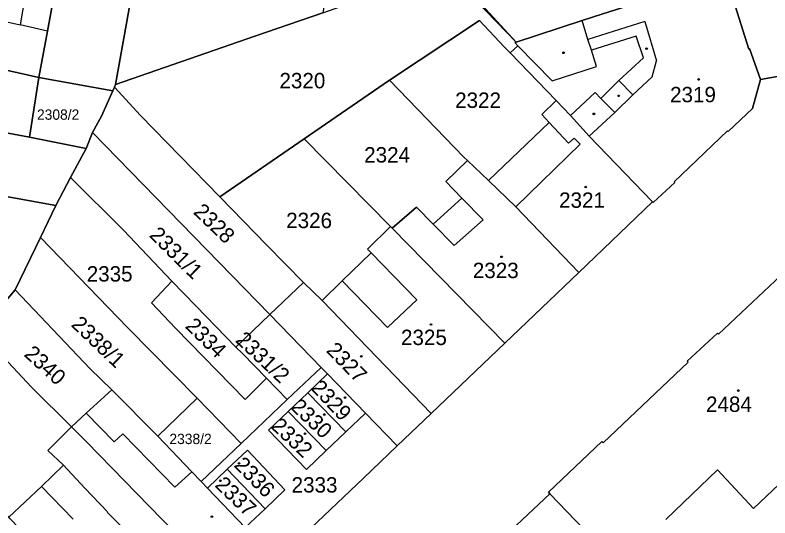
# Model space of a CAD drawing. Extents: x -596233 to -595156, y -1161235 to -1159375.
# Drawn here: x -595870.4 to -595787.2, y -1160442.5 to -1160387 of the extents above; entities that cross this region are included whole.
import ezdxf

# ---------------------------------------------------------------- set-up
doc = ezdxf.new("R2010")
doc.units = 0
for name, color, linetype in [('KN_CAR_KR', 7, 'Continuous'), ('KN_KULTURY', 7, 'Continuous'), ('KN_PARC_CIS_POZ', 7, 'Continuous'), ('KN_PARC_CIS_STAV', 7, 'Continuous'), ('KN_PARC_PLOCHA', 7, 'Continuous'), ('parcely_l', 7, 'Continuous')]:
    doc.layers.add(name, color=color, linetype=linetype)

msp = doc.modelspace()

# ---------------------------------------------------------------- linework, layer by layer
at = {"layer": 'KN_CAR_KR'}
for points in [[(-595865.68, -1160363.58), (-595869.81, -1160388.06)], [(-595873.45, -1160387.23), (-595869.81, -1160388.06)], [(-595807.22, -1160389.66), (-595807.86, -1160387.59)], [(-595800.95, -1160387.7), (-595807.22, -1160389.66)], [(-595800.95, -1160387.7), (-595799.67, -1160392.04)], [(-595866.8, -1160388.74), (-595869.81, -1160388.06)], [(-595801.9, -1160389.3), (-595806.81, -1160390.84)], [(-595801.08, -1160391.71), (-595801.9, -1160389.3)], [(-595814.95, -1160390.36), (-595811.17, -1160394.23)], [(-595806.81, -1160390.84), (-595807.22, -1160389.66)], [(-595806.26, -1160392.65), (-595806.81, -1160390.84)], [(-595803.8, -1160394.21), (-595801.08, -1160391.71)], [(-595811.17, -1160394.23), (-595806.26, -1160392.65)], [(-595800.14, -1160393.78), (-595799.67, -1160392.04)], [(-595805.79, -1160396.2), (-595803.8, -1160394.21)], [(-595803.8, -1160394.21), (-595802.25, -1160395.77)], [(-595802.25, -1160395.77), (-595800.14, -1160393.78)], [(-595809.12, -1160398.06), (-595806.43, -1160395.53)], [(-595806.43, -1160395.53), (-595805.79, -1160396.2)], [(-595804.25, -1160397.73), (-595802.25, -1160395.77)], [(-595805.79, -1160396.2), (-595804.25, -1160397.73)], [(-595807.09, -1160400.34), (-595804.25, -1160397.73)], [(-595811.49, -1160398.84), (-595809.36, -1160401.13)], [(-595809.36, -1160401.13), (-595808.75, -1160400.55)], [(-595808.75, -1160400.55), (-595808.07, -1160401.23)], [(-595808.07, -1160401.23), (-595815.17, -1160408.13)], [(-595818.77, -1160409.59), (-595821.1, -1160407.2)], [(-595824.27, -1160410.07), (-595821.95, -1160412.42)], [(-595821.95, -1160412.42), (-595818.77, -1160409.59)], [(-595831.12, -1160413.22), (-595826.09, -1160418.39)], [(-595829.31, -1160421.46), (-595834.31, -1160416.31)], [(-595826.09, -1160418.39), (-595829.31, -1160421.46)], [(-595859.44, -1160434.09), (-595862.55, -1160430.93)], [(-595779.11, -1160432.11), (-595788.96, -1160441.45)], [(-595858.51, -1160433.19), (-595859.44, -1160434.09)], [(-595852.75, -1160439.09), (-595858.51, -1160433.19)], [(-595865.02, -1160436.67), (-595862.67, -1160439.2)], [(-595850.9, -1160437.38), (-595852.75, -1160439.09)], [(-595792.92, -1160437.19), (-595798.64, -1160442.64)], [(-595788.96, -1160441.45), (-595792.92, -1160437.19)], [(-595867.48, -1160439), (-595863.97, -1160442.6)], [(-595862.67, -1160439.2), (-595860.17, -1160441.8)], [(-595860.17, -1160441.8), (-595860.23, -1160441.86)], [(-595860.23, -1160441.86), (-595856.25, -1160445.86)]]:
    msp.add_lwpolyline(points, dxfattribs=at)
at = {"layer": 'KN_KULTURY'}
for centre, radius in [((-595809.9, -1160391.14), 0.09), ((-595809.9, -1160391.14), 0.0398), ((-595800.75, -1160390.68), 0.09), ((-595800.75, -1160390.68), 0.0398), ((-595795.01, -1160394.08), 0.09), ((-595795.01, -1160394.08), 0.0398), ((-595803.83, -1160395.89), 0.09), ((-595803.83, -1160395.89), 0.0398), ((-595806.56, -1160397.88), 0.09), ((-595806.56, -1160397.88), 0.0398), ((-595807.46, -1160405.96), 0.09), ((-595807.46, -1160405.96), 0.0398), ((-595816.74, -1160413.66), 0.09), ((-595816.74, -1160413.66), 0.0398), ((-595824.52, -1160421.13), 0.09), ((-595824.52, -1160421.13), 0.0398), ((-595832.2, -1160424.65), 0.09), ((-595832.2, -1160424.65), 0.0398), ((-595790.64, -1160428.42), 0.09), ((-595790.64, -1160428.42), 0.0398), ((-595834, -1160429.19), 0.09), ((-595834, -1160429.19), 0.0398), ((-595836.28, -1160431.07), 0.09), ((-595836.28, -1160431.07), 0.0398), ((-595838.41, -1160433.18), 0.09), ((-595838.41, -1160433.18), 0.0398), ((-595845.69, -1160436.46), 0.09), ((-595845.69, -1160436.46), 0.0398), ((-595847.75, -1160438.38), 0.09), ((-595847.75, -1160438.38), 0.0398), ((-595848.68, -1160442.34), 0.09), ((-595848.68, -1160442.34), 0.0398)]:
    msp.add_circle(centre, radius, dxfattribs=at)
at = {"layer": 'KN_PARC_PLOCHA'}
for points in [[(-595858.59, -1160340.56), (-595860.41, -1160351.1), (-595860.54, -1160351.8), (-595861.06, -1160355.69), (-595862.48, -1160364.12), (-595863.62, -1160370.91), (-595863.68, -1160371.29), (-595864.11, -1160374.06), (-595866.8, -1160388.74), (-595867.74, -1160393.87), (-595881.13, -1160390.85), (-595878.76, -1160378.19), (-595876.93, -1160368.38), (-595875.78, -1160362.24), (-595875.17, -1160358.96), (-595873.01, -1160347.61), (-595871.3, -1160338.04), (-595863.4, -1160339.61), (-595863.37, -1160339.46), (-595858.55, -1160340.36)], [(-595792.06, -1160382.52), (-595805.56, -1160386.84), (-595807.86, -1160387.59), (-595815.14, -1160389.97), (-595820.61, -1160383.98), (-595815.78, -1160382.47), (-595815.35, -1160383.84), (-595805.04, -1160380.63), (-595806.23, -1160376.85), (-595804.59, -1160376.28), (-595794.98, -1160373.26)], [(-595855.78, -1160374.96), (-595859.29, -1160394.64), (-595859.43, -1160394.95), (-595859.6, -1160395.34), (-595867.74, -1160393.87), (-595866.8, -1160388.74), (-595864.11, -1160374.06), (-595858.75, -1160375)], [(-595844.98, -1160375.17), (-595839.04, -1160375.28), (-595834.51, -1160375.37), (-595836.46, -1160386.72), (-595843.93, -1160389.3), (-595859.29, -1160394.64), (-595855.78, -1160374.96)], [(-595815.14, -1160389.97), (-595822.83, -1160381.93), (-595815.83, -1160379.67), (-595810.75, -1160378.3), (-595806.23, -1160376.85), (-595805.04, -1160380.63), (-595815.35, -1160383.84), (-595815.78, -1160382.47), (-595820.61, -1160383.98)], [(-595815.14, -1160389.97), (-595815.27, -1160390.02), (-595814.95, -1160390.36), (-595815.8, -1160391.15), (-595816.45, -1160390.48), (-595819.17, -1160387.56), (-595829.08, -1160394.15), (-595838.49, -1160400.65), (-595847.79, -1160407.03), (-595856.56, -1160398.05), (-595859.43, -1160394.95), (-595859.29, -1160394.64), (-595843.93, -1160389.3), (-595836.46, -1160386.72), (-595832.57, -1160385.37), (-595822.83, -1160381.93)], [(-595788.2, -1160394.1), (-595789.07, -1160397.3), (-595791.75, -1160399.82), (-595791.82, -1160399.75), (-595797.7, -1160405.38), (-595797.63, -1160405.45), (-595800.01, -1160407.66), (-595800.08, -1160407.59), (-595807.09, -1160400.34), (-595809.12, -1160398.06), (-595810.73, -1160396.39), (-595815.8, -1160391.15), (-595814.95, -1160390.36), (-595815.27, -1160390.02), (-595815.14, -1160389.97), (-595807.86, -1160387.59), (-595805.56, -1160386.84), (-595792.06, -1160382.52), (-595789.47, -1160390.73), (-595789.39, -1160390.68)], [(-595815.8, -1160391.15), (-595810.73, -1160396.39), (-595812.31, -1160397.96), (-595811.49, -1160398.84), (-595818.18, -1160405.24), (-595820.51, -1160403.01), (-595820.88, -1160402.65), (-595829.08, -1160394.15), (-595819.17, -1160387.56), (-595816.45, -1160390.48)], [(-595900.72, -1160394.38), (-595892.74, -1160395.91), (-595883.15, -1160397.75), (-595882.92, -1160397.8), (-595868.8, -1160400.45), (-595862.55, -1160401.69), (-595864.25, -1160404.89), (-595865.9, -1160408.01), (-595873.02, -1160406.69), (-595875.63, -1160406.2), (-595878.11, -1160405.74), (-595890.43, -1160403.4), (-595907.71, -1160400.15), (-595906.63, -1160394.38), (-595912.54, -1160393.29), (-595913.62, -1160399.04), (-595919.92, -1160397.86), (-595918.74, -1160390.93), (-595904.64, -1160393.63)], [(-595881.13, -1160390.85), (-595867.74, -1160393.87), (-595868.8, -1160400.45), (-595882.92, -1160397.8), (-595883.15, -1160397.75), (-595881.8, -1160390.72)], [(-595859.6, -1160395.34), (-595860.85, -1160398.14), (-595861.84, -1160399.93), (-595862.55, -1160401.69), (-595868.8, -1160400.45), (-595867.74, -1160393.87)], [(-595820.51, -1160403.01), (-595822.9, -1160405.35), (-595821.1, -1160407.2), (-595824.27, -1160410.07), (-595826.13, -1160408.18), (-595828.79, -1160410.51), (-595828.97, -1160410.32), (-595838.49, -1160400.65), (-595829.08, -1160394.15), (-595820.88, -1160402.65)], [(-595847.79, -1160407.03), (-595842.63, -1160412.37), (-595838.56, -1160416.51), (-595842.3, -1160420.04), (-595861.84, -1160399.93), (-595860.85, -1160398.14), (-595859.6, -1160395.34), (-595859.43, -1160394.95), (-595856.56, -1160398.05)], [(-595800.08, -1160407.59), (-595808.22, -1160415.38), (-595815.17, -1160408.13), (-595818.18, -1160405.24), (-595811.49, -1160398.84), (-595812.31, -1160397.96), (-595810.73, -1160396.39), (-595809.12, -1160398.06), (-595807.09, -1160400.34)], [(-595913.62, -1160399.04), (-595907.71, -1160400.15), (-595890.43, -1160403.4), (-595878.11, -1160405.74), (-595875.63, -1160406.2), (-595873.02, -1160406.69), (-595865.9, -1160408.01), (-595867.58, -1160411.51), (-595870.37, -1160417.31), (-595874.3, -1160421.94), (-595874.98, -1160422.78), (-595882, -1160431.18), (-595885.83, -1160435.77), (-595894.39, -1160426.85), (-595893.37, -1160420.66), (-595892.78, -1160417.12), (-595891.8, -1160411.16), (-595903.68, -1160408.85), (-595904.75, -1160408.62), (-595910.92, -1160407.3), (-595912.15, -1160407.04), (-595921.23, -1160405.32), (-595919.92, -1160397.86)], [(-595842.3, -1160420.04), (-595846.03, -1160423.62), (-595850.45, -1160419.06), (-595853.09, -1160416.36), (-595858.43, -1160410.73), (-595864.25, -1160404.89), (-595862.55, -1160401.69), (-595861.84, -1160399.93)], [(-595828.97, -1160410.32), (-595831.53, -1160412.8), (-595831.12, -1160413.22), (-595834.31, -1160416.31), (-595836.51, -1160418.49), (-595838.56, -1160416.51), (-595842.63, -1160412.37), (-595847.79, -1160407.03), (-595838.49, -1160400.65)], [(-595818.18, -1160405.24), (-595815.17, -1160408.13), (-595808.22, -1160415.38), (-595816.38, -1160423.2), (-595828.79, -1160410.51), (-595826.13, -1160408.18), (-595824.27, -1160410.07), (-595821.1, -1160407.2), (-595822.9, -1160405.35), (-595820.51, -1160403.01)], [(-595853.09, -1160416.36), (-595855.35, -1160418.75), (-595852.68, -1160421.52), (-595845, -1160429.4), (-595842.66, -1160427.06), (-595840.36, -1160429.42), (-595845.45, -1160434.27), (-595850.3, -1160429.25), (-595857.94, -1160421.49), (-595867.58, -1160411.51), (-595865.9, -1160408.01), (-595864.25, -1160404.89), (-595858.43, -1160410.73)], [(-595828.79, -1160410.51), (-595816.38, -1160423.2), (-595824.49, -1160430.95), (-595836.51, -1160418.49), (-595834.31, -1160416.31), (-595831.12, -1160413.22), (-595831.53, -1160412.8), (-595828.97, -1160410.32)], [(-595850.3, -1160429.25), (-595854.63, -1160433.44), (-595859.72, -1160428.34), (-595862.11, -1160426.01), (-595870.37, -1160417.31), (-595867.58, -1160411.51), (-595857.94, -1160421.49)], [(-595846.03, -1160423.62), (-595845.31, -1160424.34), (-595842.66, -1160427.06), (-595845, -1160429.4), (-595852.68, -1160421.52), (-595855.35, -1160418.75), (-595853.09, -1160416.36), (-595850.45, -1160419.06)], [(-595836.51, -1160418.49), (-595824.49, -1160430.95), (-595828.23, -1160434.52), (-595831.73, -1160430.92), (-595835.93, -1160426.59), (-595836.63, -1160425.87), (-595842.3, -1160420.04), (-595838.56, -1160416.51)], [(-595859.72, -1160428.34), (-595862.55, -1160430.93), (-595864.16, -1160432.41), (-595868.55, -1160428.03), (-595874.3, -1160421.94), (-595870.37, -1160417.31), (-595862.11, -1160426.01)], [(-595836.63, -1160425.87), (-595840.36, -1160429.42), (-595842.66, -1160427.06), (-595845.31, -1160424.34), (-595846.03, -1160423.62), (-595842.3, -1160420.04)], [(-595864.16, -1160432.41), (-595866.76, -1160435.02), (-595865.02, -1160436.67), (-595867.48, -1160439), (-595871.07, -1160442.41), (-595876.59, -1160436.68), (-595882, -1160431.18), (-595874.98, -1160422.78), (-595874.3, -1160421.94), (-595868.55, -1160428.03)], [(-595835.93, -1160426.59), (-595838.1, -1160428.66), (-595840.28, -1160430.73), (-595842.45, -1160432.8), (-595838.25, -1160437.12), (-595836.08, -1160435.05), (-595833.9, -1160432.99), (-595831.73, -1160430.92), (-595828.23, -1160434.52), (-595831.96, -1160438.08), (-595837.06, -1160442.96), (-595841.55, -1160447.17), (-595845.01, -1160443.54), (-595842.82, -1160441.46), (-595840.63, -1160439.38), (-595844.76, -1160435), (-595846.98, -1160437.11), (-595849.16, -1160439.18), (-595849.85, -1160438.45), (-595845.45, -1160434.27), (-595840.36, -1160429.42), (-595836.63, -1160425.87)], [(-595831.73, -1160430.92), (-595833.9, -1160432.99), (-595838.1, -1160428.66), (-595835.93, -1160426.59)], [(-595854.63, -1160433.44), (-595850.9, -1160437.38), (-595849.85, -1160438.45), (-595849.16, -1160439.18), (-595845.01, -1160443.54), (-595841.55, -1160447.17), (-595845.8, -1160451.23), (-595862.49, -1160434.07), (-595864.16, -1160432.41), (-595862.55, -1160430.93), (-595859.72, -1160428.34)], [(-595845.45, -1160434.27), (-595849.85, -1160438.45), (-595850.9, -1160437.38), (-595854.63, -1160433.44), (-595850.3, -1160429.25)], [(-595833.9, -1160432.99), (-595836.08, -1160435.05), (-595840.28, -1160430.73), (-595838.1, -1160428.66)], [(-595836.08, -1160435.05), (-595838.25, -1160437.12), (-595842.45, -1160432.8), (-595840.28, -1160430.73)], [(-595845.8, -1160451.23), (-595854.57, -1160459.53), (-595870.96, -1160442.53), (-595871.07, -1160442.41), (-595867.48, -1160439), (-595865.02, -1160436.67), (-595866.76, -1160435.02), (-595864.16, -1160432.41), (-595862.49, -1160434.07)], [(-595842.82, -1160441.46), (-595846.98, -1160437.11), (-595844.76, -1160435), (-595840.63, -1160439.38)], [(-595842.82, -1160441.46), (-595845.01, -1160443.54), (-595849.16, -1160439.18), (-595846.98, -1160437.11)], [(-595793.83, -1160470.75), (-595796.23, -1160471.82), (-595798.63, -1160472.88), (-595801.78, -1160474.29), (-595803.29, -1160474.96), (-595803.52, -1160474.43), (-595807.17, -1160476.08), (-595811.47, -1160478.36), (-595817.12, -1160465.97), (-595819.11, -1160461.5), (-595821.3, -1160456.69), (-595819.9, -1160455.4), (-595823.66, -1160451.32), (-595811.43, -1160439.81), (-595803.85, -1160447.7), (-595803.68, -1160447.88), (-595802.69, -1160450.29), (-595799.86, -1160456.8), (-595798.35, -1160460.26), (-595796.73, -1160464.19), (-595795.91, -1160466.03), (-595794.67, -1160468.86)]]:
    msp.add_lwpolyline(points, close=True, dxfattribs=at)
for points in [[(-595765.65, -1160390.07), (-595788.2, -1160394.1), (-595789.39, -1160390.68), (-595789.47, -1160390.73), (-595792.06, -1160382.52), (-595794.98, -1160373.26), (-595797.88, -1160364.04), (-595800.45, -1160355.88), (-595801.56, -1160352.29), (-595803.84, -1160350.29), (-595784.68, -1160354.18)], [(-595877.54, -1160481.41), (-595867.6, -1160471.87), (-595861.39, -1160465.99), (-595854.57, -1160459.53), (-595845.8, -1160451.23), (-595841.55, -1160447.17), (-595837.06, -1160442.96), (-595831.96, -1160438.08), (-595828.23, -1160434.52), (-595824.49, -1160430.95), (-595816.38, -1160423.2), (-595808.22, -1160415.38), (-595800.08, -1160407.59), (-595800.01, -1160407.66), (-595797.63, -1160405.45), (-595797.7, -1160405.38), (-595791.82, -1160399.75), (-595791.75, -1160399.82), (-595789.07, -1160397.3), (-595788.2, -1160394.1), (-595765.65, -1160390.07)], [(-595783.44, -1160413.37), (-595792.81, -1160422.21), (-595792.94, -1160422.07), (-595796.26, -1160425.19), (-595796.15, -1160425.3), (-595805.54, -1160434.19), (-595805.67, -1160434.06), (-595811.58, -1160439.65), (-595811.43, -1160439.81), (-595823.66, -1160451.32), (-595833.07, -1160460.01), (-595833.22, -1160459.91), (-595836.93, -1160463.4), (-595836.82, -1160463.51), (-595844.21, -1160470.5), (-595851.78, -1160477.77)], [(-595792.24, -1160474.3), (-595793.83, -1160470.75), (-595794.67, -1160468.86), (-595795.91, -1160466.03), (-595796.73, -1160464.19), (-595798.35, -1160460.26), (-595799.86, -1160456.8), (-595802.69, -1160450.29), (-595803.68, -1160447.88), (-595803.85, -1160447.7), (-595811.43, -1160439.81), (-595811.58, -1160439.65), (-595805.67, -1160434.06), (-595805.54, -1160434.19), (-595796.15, -1160425.3), (-595796.26, -1160425.19), (-595792.94, -1160422.07), (-595792.81, -1160422.21), (-595783.44, -1160413.37)]]:
    msp.add_lwpolyline(points, dxfattribs=at)
at = {"layer": 'parcely_l'}
for points in [[(-595864.11, -1160374.06), (-595866.8, -1160388.74), (-595867.74, -1160393.87)], [(-595859.29, -1160394.64), (-595855.78, -1160374.96)], [(-595806.23, -1160376.85), (-595805.04, -1160380.63), (-595815.35, -1160383.84), (-595815.78, -1160382.47), (-595820.61, -1160383.98), (-595815.14, -1160389.97)], [(-595815.14, -1160389.97), (-595822.83, -1160381.93)], [(-595815.14, -1160389.97), (-595807.86, -1160387.59), (-595805.56, -1160386.84), (-595792.06, -1160382.52)], [(-595792.06, -1160382.52), (-595789.47, -1160390.73), (-595789.39, -1160390.68), (-595788.2, -1160394.1)], [(-595836.46, -1160386.72), (-595843.93, -1160389.3), (-595859.29, -1160394.64)], [(-595815.8, -1160391.15), (-595816.45, -1160390.48), (-595819.17, -1160387.56), (-595829.08, -1160394.15)], [(-595815.8, -1160391.15), (-595814.95, -1160390.36), (-595815.27, -1160390.02), (-595815.14, -1160389.97)], [(-595788.2, -1160394.1), (-595765.65, -1160390.07)], [(-595867.74, -1160393.87), (-595881.13, -1160390.85)], [(-595810.73, -1160396.39), (-595815.8, -1160391.15)], [(-595867.74, -1160393.87), (-595868.8, -1160400.45)], [(-595867.74, -1160393.87), (-595859.6, -1160395.34)], [(-595829.08, -1160394.15), (-595838.49, -1160400.65)], [(-595829.08, -1160394.15), (-595820.88, -1160402.65), (-595820.51, -1160403.01)], [(-595788.2, -1160394.1), (-595789.07, -1160397.3), (-595791.75, -1160399.82), (-595791.82, -1160399.75), (-595797.7, -1160405.38), (-595797.63, -1160405.45), (-595800.01, -1160407.66), (-595800.08, -1160407.59)], [(-595861.84, -1160399.93), (-595860.85, -1160398.14), (-595859.6, -1160395.34)], [(-595859.6, -1160395.34), (-595859.43, -1160394.95)], [(-595859.43, -1160394.95), (-595859.29, -1160394.64)], [(-595859.43, -1160394.95), (-595856.56, -1160398.05), (-595847.79, -1160407.03)], [(-595818.18, -1160405.24), (-595811.49, -1160398.84), (-595812.31, -1160397.96), (-595810.73, -1160396.39)], [(-595800.08, -1160407.59), (-595807.09, -1160400.34), (-595809.12, -1160398.06), (-595810.73, -1160396.39)], [(-595883.15, -1160397.75), (-595882.92, -1160397.8), (-595868.8, -1160400.45)], [(-595907.71, -1160400.15), (-595890.43, -1160403.4), (-595878.11, -1160405.74), (-595875.63, -1160406.2), (-595873.02, -1160406.69), (-595865.9, -1160408.01)], [(-595862.55, -1160401.69), (-595861.84, -1160399.93)], [(-595861.84, -1160399.93), (-595842.3, -1160420.04)], [(-595868.8, -1160400.45), (-595862.55, -1160401.69)], [(-595838.49, -1160400.65), (-595847.79, -1160407.03)], [(-595838.49, -1160400.65), (-595828.97, -1160410.32)], [(-595862.55, -1160401.69), (-595864.25, -1160404.89)], [(-595828.79, -1160410.51), (-595826.13, -1160408.18), (-595824.27, -1160410.07), (-595821.1, -1160407.2), (-595822.9, -1160405.35), (-595820.51, -1160403.01)], [(-595820.51, -1160403.01), (-595818.18, -1160405.24)], [(-595864.25, -1160404.89), (-595865.9, -1160408.01)], [(-595853.09, -1160416.36), (-595858.43, -1160410.73), (-595864.25, -1160404.89)], [(-595808.22, -1160415.38), (-595815.17, -1160408.13), (-595818.18, -1160405.24)], [(-595847.79, -1160407.03), (-595842.63, -1160412.37), (-595838.56, -1160416.51)], [(-595811.43, -1160439.81), (-595811.58, -1160439.65), (-595805.67, -1160434.06), (-595805.54, -1160434.19), (-595796.15, -1160425.3), (-595796.26, -1160425.19), (-595792.94, -1160422.07), (-595792.81, -1160422.21), (-595783.44, -1160413.37), (-595783.54, -1160413.26), (-595777.58, -1160407.51)], [(-595800.08, -1160407.59), (-595808.22, -1160415.38)], [(-595865.9, -1160408.01), (-595867.58, -1160411.51)], [(-595836.51, -1160418.49), (-595834.31, -1160416.31), (-595831.12, -1160413.22), (-595831.53, -1160412.8), (-595828.97, -1160410.32)], [(-595828.97, -1160410.32), (-595828.79, -1160410.51)], [(-595816.38, -1160423.2), (-595828.79, -1160410.51)], [(-595867.58, -1160411.51), (-595870.37, -1160417.31)], [(-595867.58, -1160411.51), (-595857.94, -1160421.49), (-595850.3, -1160429.25)], [(-595808.22, -1160415.38), (-595816.38, -1160423.2)], [(-595842.66, -1160427.06), (-595845, -1160429.4), (-595852.68, -1160421.52), (-595855.35, -1160418.75), (-595853.09, -1160416.36)], [(-595853.09, -1160416.36), (-595850.45, -1160419.06), (-595846.03, -1160423.62)], [(-595842.3, -1160420.04), (-595838.56, -1160416.51)], [(-595838.56, -1160416.51), (-595836.51, -1160418.49)], [(-595870.37, -1160417.31), (-595874.3, -1160421.94)], [(-595859.72, -1160428.34), (-595862.11, -1160426.01), (-595870.37, -1160417.31)], [(-595836.51, -1160418.49), (-595824.49, -1160430.95)], [(-595842.3, -1160420.04), (-595846.03, -1160423.62)], [(-595836.63, -1160425.87), (-595842.3, -1160420.04)], [(-595864.16, -1160432.41), (-595868.55, -1160428.03), (-595874.3, -1160421.94)], [(-595846.03, -1160423.62), (-595845.31, -1160424.34), (-595842.66, -1160427.06)], [(-595824.49, -1160430.95), (-595816.38, -1160423.2)], [(-595840.36, -1160429.42), (-595836.63, -1160425.87)], [(-595835.93, -1160426.59), (-595836.63, -1160425.87)], [(-595835.93, -1160426.59), (-595838.1, -1160428.66)], [(-595831.73, -1160430.92), (-595835.93, -1160426.59)], [(-595842.66, -1160427.06), (-595840.36, -1160429.42)], [(-595864.16, -1160432.41), (-595862.55, -1160430.93), (-595859.72, -1160428.34)], [(-595854.63, -1160433.44), (-595859.72, -1160428.34)], [(-595850.3, -1160429.25), (-595854.63, -1160433.44)], [(-595845.45, -1160434.27), (-595850.3, -1160429.25)], [(-595845.45, -1160434.27), (-595840.36, -1160429.42)], [(-595838.1, -1160428.66), (-595840.28, -1160430.73)], [(-595838.1, -1160428.66), (-595833.9, -1160432.99)], [(-595840.28, -1160430.73), (-595842.45, -1160432.8), (-595838.25, -1160437.12), (-595836.08, -1160435.05)], [(-595836.08, -1160435.05), (-595840.28, -1160430.73)], [(-595833.9, -1160432.99), (-595831.73, -1160430.92)], [(-595828.23, -1160434.52), (-595831.73, -1160430.92)], [(-595824.49, -1160430.95), (-595828.23, -1160434.52)], [(-595871.07, -1160442.41), (-595867.48, -1160439), (-595865.02, -1160436.67), (-595866.76, -1160435.02), (-595864.16, -1160432.41)], [(-595845.8, -1160451.23), (-595862.49, -1160434.07), (-595864.16, -1160432.41)], [(-595854.63, -1160433.44), (-595850.9, -1160437.38), (-595849.85, -1160438.45)], [(-595836.08, -1160435.05), (-595833.9, -1160432.99)], [(-595849.85, -1160438.45), (-595845.45, -1160434.27)], [(-595842.82, -1160441.46), (-595840.63, -1160439.38), (-595844.76, -1160435), (-595846.98, -1160437.11)], [(-595828.23, -1160434.52), (-595831.96, -1160438.08), (-595837.06, -1160442.96), (-595841.55, -1160447.17)], [(-595849.16, -1160439.18), (-595846.98, -1160437.11)], [(-595846.98, -1160437.11), (-595842.82, -1160441.46)], [(-595849.85, -1160438.45), (-595849.16, -1160439.18)], [(-595845.01, -1160443.54), (-595849.16, -1160439.18)], [(-595823.66, -1160451.32), (-595811.43, -1160439.81)], [(-595811.43, -1160439.81), (-595803.85, -1160447.7), (-595803.68, -1160447.88), (-595802.69, -1160450.29), (-595799.86, -1160456.8), (-595798.35, -1160460.26), (-595796.73, -1160464.19), (-595795.91, -1160466.03), (-595794.67, -1160468.86), (-595793.83, -1160470.75)], [(-595842.82, -1160441.46), (-595845.01, -1160443.54)]]:
    msp.add_lwpolyline(points, dxfattribs=at)

# ---------------------------------------------------------------- texts
at = {"layer": 'KN_PARC_CIS_POZ'}
for s, height, p in [('2320', 1.7, (-595841.2266, -1160395.06)), ('2322', 1.7, (-595821.8566, -1160397.22)), ('2308/2', 1.14, (-595867.96, -1160398.53)), ('2324', 1.7, (-595831.8866, -1160403.25)), ('2326', 1.7, (-595840.4866, -1160410.49)), ('2335', 1.7, (-595862.4766, -1160416.39)), ('2338/2', 1.14, (-595853.36, -1160434.33)), ('2333', 1.7, (-595839.8866, -1160439.68))]:
    msp.add_text(s, height=height, dxfattribs=at).set_placement(p)
for s, rotation, p in [('2328', 316.167875, (-595850.8083, -1160408.8216)), ('2331/1', 315.209722, (-595855.6783, -1160411.3666)), ('2338/1', 316.369676, (-595864.2863, -1160421.2465)), ('2334', 315.300275, (-595851.7153, -1160421.4078)), ('2331/2', 316.75428, (-595846.1685, -1160422.97)), ('2340', 317.371955, (-595869.4831, -1160424.5293))]:
    msp.add_text(s, height=1.7, rotation=rotation, dxfattribs=at).set_placement(p)
at = {"layer": 'KN_PARC_CIS_STAV'}
for s, p in [('2319', (-595798.1566, -1160396.6)), ('2321', (-595810.3966, -1160408.25)), ('2323', (-595819.9066, -1160416.01)), ('2325', (-595827.8266, -1160423.4)), ('2484', (-595794.1966, -1160430.78))]:
    msp.add_text(s, height=1.7, dxfattribs=at).set_placement(p)
for s, rotation, p in [('2327', 314.250692, (-595836.1648, -1160424.0776)), ('2329', 313.201812, (-595837.8436, -1160428.2181)), ('2330', 316.47965, (-595840.09, -1160430.3638)), ('2332', 316.695166, (-595842.258, -1160432.4824)), ('2336', 314.34413, (-595846.3284, -1160436.7411)), ('2337', 316.170695, (-595848.4484, -1160438.9517))]:
    msp.add_text(s, height=1.7, rotation=rotation, dxfattribs=at).set_placement(p)

doc.saveas('drawing.dxf')
